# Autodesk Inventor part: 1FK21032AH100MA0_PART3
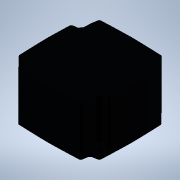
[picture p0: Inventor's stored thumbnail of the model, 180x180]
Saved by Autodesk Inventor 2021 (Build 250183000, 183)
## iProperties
Created: 2025-04
Part Number: 1FK21032AH100MA0_PART3
Material: Generic
Catalog Web Link: www.3dfindit.com
Description: -Servo synchronous motor
Document SubType Name: Modeling
Designer: psAdmin
Mass: 116.584 g
Surface Area: 147.122 cm^2
Volume: 116.584 cm^3
Density: 1 g/cm^3
Appearance: PSOLRGB-38-46-56
Category: PARTsolutions
Title: 1FK21032AH100MA0_PART3
Author: Cadenas PARTsolutions
Comments: Servo synchronous motor
Sending System: PARTsolutions
Preprocessor: ST-DEVELOPER v19.3
PSOL_IDENT_0: {$CADENAS_DATA/23d-libs/siemens_ag/_cat_/12/33/1fk21032ah100ma0.prj},213 {VTYP=3D},{NB=1FK21032AH100
PSOL_IDENT_1: MA0_PART3},{LINA=1FK21032AH100MA0_PART3},{NN=1FK21032AH100MA0_PART3},{NOPRJ=TRUE},{DATE=19.08.2025 1
PSOL_IDENT_2: 4:00:27},{GEOMDATE=30.07.2025 02:02:58},{VERSION=},{LINEID=10},{WBVAR=},{WBNUMERIC=}  {NB=1FK21032AH
PSOL_IDENT_3: 100MA0_PART3},{LINA=1FK21032AH100MA0_PART3},{KT=DUMMY},{PREVIEW=../../../_pool_/d3/78/p_d211_xx_0093
PSOL_IDENT_4: 4j.png},{DESCSHORT=SIMOTICS S-1FK2 HD, SINAMICS S210 3AC 400V-480V, 0.59 Nm, 4500 rpm},{DESCLONG=SIM
PSOL_IDENT_5: OTICS S-1FK2 HD servo motor M0=0.64 Nm; PN = 0.28 kW at nN=4500 rpm (380-480 V); PN = 0.167 kW at nN=
PSOL_IDENT_6: 2500 rpm (200-240 V); with holding brake; degree of protection IP64; cylindrical shaft D14 x 30 mm;
PSOL_IDENT_7: absolute encoder 22-bit + 12-bit multiturn (encoder AM22DQC); with OCC interface; plug size M17, rot
PSOL_IDENT_8: atable; SIMOTICS S-1FK2 servomotorfor a wide range of uses in industrial environments. SIMOTICS S‑1F
PSOL_IDENT_9: K2 servomotors are compact synchronous motors with a high dynamic performance that set themselves ap
PSOL_IDENT_10: art as a result of their high power density, degree of protection and overload capability. The motor
PSOL_IDENT_11: s are available in two variants: as High Dynamic variant (highest dynamic performance as a result of
PSOL_IDENT_12: the low intrinsic moment of inertia for applications demanding a high dynamic performance with low
PSOL_IDENT_13: moved masses) - and as Compact variant (precise and stable closed-loop control for medium up to larg
PSOL_IDENT_14: e moved masses as a result of a medium intrinsic moment of inertia). SIMOTICSS‑1FK2 servomotors full
PSOL_IDENT_15: y exploit their strengths in a system with the SINAMICSS210 frequency converter and simple connectio
PSOL_IDENT_16: n using the one cable connection (OCC). Advantages include the short control and positioning times,
PSOL_IDENT_17: fast and precise correction of disturbing quantities as well as stable control with a high dynamic p
PSOL_IDENT_18: erformance. The servo motors can be configured to address a wide range of requirements. For example
PSOL_IDENT_19: with and without holding brake, IP64 or IP65 degree of protection, singleturn or multiturn absolute
PSOL_IDENT_20: encoders - to name just a few. Further, the servomotors are available in different shaft heights ext
PSOL_IDENT_21: ending from 20 to 100. A shaft sealing ring is available to achieve an IP65 degree of protection and
PSOL_IDENT_22: for subsequent mounting at the motor or as spare part. SIMOTICS - the optimum motor for each and ev
PSOL_IDENT_23: ery motion control application.},{INTNO=195125315563},{SUPPLIERALTNO=1FK2103-2AH10-0MA0},{MANUID=1FK
PSOL_IDENT_24: 21032AH100MA0},{MANUNAME=Siemens},{MANUTYPEDESC=SYNCHRONOUS MOTOR 1FK2 HD 0,64 NM},{AAU732=SIMOTICS}
PSOL_IDENT_25: ,{AAO057=S-1FK2},{AAU734=SIMOTICS S-1FK2 HD servo motor M0=0.64 Nm; PN = 0.28 kW at nN=4500 rpm (380
PSOL_IDENT_26: -480 V); PN = 0.167 kW at nN=2500 rpm (200-240 V); with holding brake; degree of protection IP64; cy
PSOL_IDENT_27: lindrical shaft D14 x 30 mm; absolute encoder 22-bit + 12-bit multiturn (encoder AM22DQC); with OCC
PSOL_IDENT_28: interface; plug size M17, rotatable;},{AAW338=SYNCHRONOUS MOTOR 1FK2 HD 0,64 NM},{AAO742=SIMOTICS},{
PSOL_IDENT_29: AAO663=4034106444723},{NOCUPEROU=1},{PRICEQUANTITY=1},{QUANTITYMIN=1},{QUANTITYINT=1},{CTN=85015100}
PSOL_IDENT_30: ,{COO=RO},{AAO676=1FK2103-2AH10-0MA0},{AAO677=Siemens AG},{ORDERUNIT=C62},{CONTENTUNIT=C62}
NB: 1FK21032AH100MA0_PART3
NT: Servo synchronous motor
NBSYN: $MANUID._PART3
LINA: 1FK21032AH100MA0_PART3
CATALOG: SIEMENS
PREVIEW: ../../../_pool_/d3/78/p_d211_xx_00934j.png
DESCSHORT: SIMOTICS S-1FK2 HD, SINAMICS S210 3AC 400V-480V, 0.59 Nm, 4500 rpm
DESCLONG: SIMOTICS S-1FK2 HD servo motor M0=0.64 Nm; PN = 0.28 kW at nN=4500 rpm (380-480 V); PN = 0.167 kW at nN=2500 rpm (200-240 V); with holding brake; degree of prot
INTNO: 195125315563
SUPPLIERALTNO: 1FK2103-2AH10-0MA0
MANUID: 1FK21032AH100MA0
MANUNAME: Siemens
MANUTYPEDESC: SYNCHRONOUS MOTOR 1FK2 HD 0,64 NM
AAU732: SIMOTICS
AAO057: S-1FK2
AAU734: SIMOTICS S-1FK2 HD servo motor M0=0.64 Nm; PN = 0.28 kW at nN=4500 rpm (380-480 V); PN = 0.167 kW at nN=2500 rpm (200-240 V); with holding brake; degree of prot
AAW338: SYNCHRONOUS MOTOR 1FK2 HD 0,64 NM
AAO742: SIMOTICS
AAO663: 4034106444723.0
NOCUPEROU: 1
PRICEQUANTITY: 1
QUANTITYMIN: 1
QUANTITYINT: 1
CTN: 85015100
COO: RO
ARTICLENO: 1FK21032AH100MA0_PART3
BOMINFO: 1FK21032AH100MA0_PART3
CREATOR: CADENAS GmbH
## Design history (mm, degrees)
feature "2025_04_17_15_06_16_0580"
body "Solid1"
